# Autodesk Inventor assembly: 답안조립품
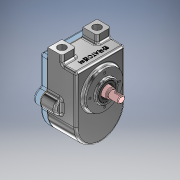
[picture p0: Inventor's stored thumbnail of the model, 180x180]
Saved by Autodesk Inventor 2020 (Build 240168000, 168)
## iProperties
Created: 2024-03
Part Number: 답안조립품
Document SubType Name: Assembly
Designer: 1강의실14
Author: 1강의실14
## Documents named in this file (9)
- C:\Users\1강의실14\Desktop\740304V1013\답안조립품.iam
- C:\Users\1강의실14\Desktop\740304V1013\본체.ipt
- C:\Users\1강의실14\Desktop\740304V1013\구동기어.ipt
- C:\Users\1강의실14\Desktop\740304V1013\스퍼기어.ipt
- C:\Users\1강의실14\Desktop\740304V1013\오일 실 14 25 7.ipt
- C:\Users\1강의실14\Desktop\740304V1013\오일레스 부시.ipt
- C:\Users\1강의실14\Desktop\740304V1013\육각 소켓 머리 볼트 M5x12.ipt
- C:\Users\1강의실14\Desktop\740304V1013\가스켓.ipt
- C:\Users\1강의실14\Desktop\740304V1013\커버.ipt
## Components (2 placed, 2 different names)
1. 가스켓:1
2. 구동기어:1
